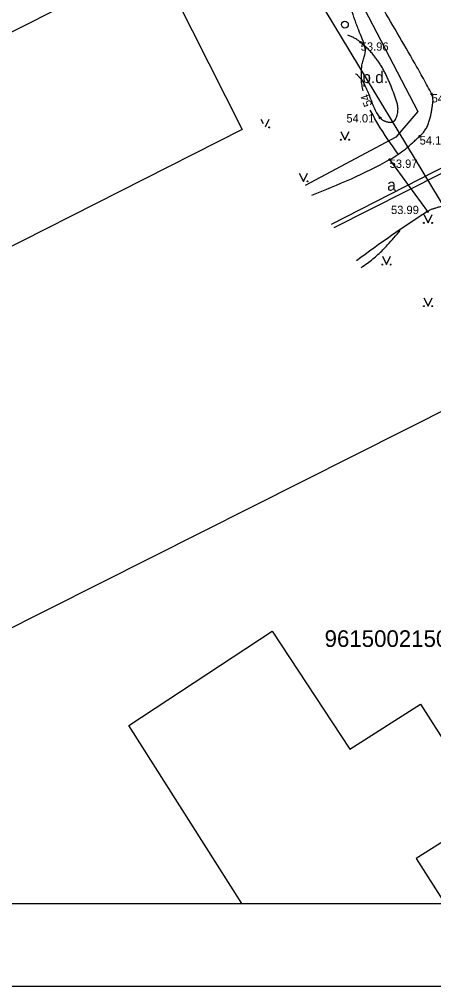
# Model space of a CAD drawing. Extents: x 578395 to 578590, y 418519 to 418816.
# Drawn here: x 578460.4 to 578485.3, y 418519.1 to 418577.2 of the extents above; entities that cross this region are included whole.
import ezdxf

# ---------------------------------------------------------------- set-up
doc = ezdxf.new("R2010")
doc.units = 0
for name, color, linetype in [('BUVE_EKAS_UZMR_####_#', 7, 'Continuous'), ('CELI_CMAL_####_####_#', 7, 'Continuous'), ('CELI_CSEG_####_TKST_#', 7, 'Continuous'), ('CELI_SEGL_####_####_#', 7, 'Continuous'), ('ELEK_VADP_ZSPR_####_#', 7, 'Continuous'), ('RAMI_PLAN_####_TKST_#', 7, 'Continuous'), ('RELJ_AATZ_####_TKST_#', 7, 'Continuous'), ('RELJ_ELEM_####_####_#', 7, 'Continuous'), ('RELJ_HORZ_####_TKST_#', 7, 'Continuous'), ('RELJ_HORZ_RESN_####_#', 7, 'Continuous'), ('ROBZ_UZMR_####_####_#', 7, 'Continuous'), ('ROBZ_UZMR_####_TKST_#', 7, 'Continuous'), ('TERT_DZOG_####_####_#', 7, 'Continuous'), ('TERT_ELEM_####_####_#', 7, 'Continuous'), ('TERT_IZMT_####_TKST_#', 7, 'Continuous'), ('TERT_KONT_####_####_#', 7, 'Continuous')]:
    doc.layers.add(name, color=color, linetype=linetype)

msp = doc.modelspace()

# ---------------------------------------------------------------- linework, layer by layer
at = {"layer": 'BUVE_EKAS_UZMR_####_#'}
for p, q in [((578449.6670000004, 418571.2860000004), (578468.6500000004, 418580.8699999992)), ((578468.6500000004, 418580.8699999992), (578473.8300000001, 418570.60999999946)), ((578473.8300000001, 418570.60999999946), (578454.6849999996, 418560.94400000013)), ((578467.0099999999, 418534.8000000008), (578475.6200000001, 418540.47000000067)), ((578475.6200000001, 418540.47000000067), (578480.2869999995, 418533.38299999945)), ((578480.2869999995, 418533.38299999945), (578484.5499999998, 418536.08999999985)), ((578484.5499999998, 418536.08999999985), (578488.6699999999, 418529.5999999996)), ((578473.7943231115, 418524.11118321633), (578467.0099999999, 418534.8000000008)), ((578488.6699999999, 418529.5999999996), (578484.2829999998, 418526.8149999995)), ((578484.2829999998, 418526.8149999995), (578486.009600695, 418524.11118321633))]:
    msp.add_line(p, q, dxfattribs=at)
at = {"layer": 'CELI_CMAL_####_####_#'}
for points in [[(578494.8535960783, 418568.01668911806), (578493.2220155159, 418570.92426636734), (578490.7633646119, 418575.52004860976), (578488.3310314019, 418580.13005654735), (578485.806, 418584.688), (578479.899, 418594.609), (578471.211, 418607.77900000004)], [(578478.0080904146, 418566.6710838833), (578482.69, 418568.81), (578483.6371195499, 418569.4394039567), (578484.068272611, 418569.823355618), (578484.2810717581, 418570.0190353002), (578484.495, 418570.212), (578484.5888582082, 418570.2964336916), (578484.6775343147, 418570.3860180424), (578484.7572642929, 418570.4852822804), (578484.8306615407, 418570.59113918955), (578484.9579047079, 418570.8222276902), (578485.0504891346, 418571.0667472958), (578485.1873221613, 418571.5887317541), (578485.2348780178, 418571.8514611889), (578485.274, 418572.107), (578485.293491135, 418572.4305135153), (578485.216, 418572.74100000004), (578484.9675876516, 418573.2094804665), (578484.7150127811, 418573.6745564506), (578484.1998261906, 418574.5962796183), (578483.1464606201, 418576.4185032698), (578482.0951147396, 418578.23622528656), (578481.5824527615, 418579.15232141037), (578481.0850000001, 418580.07800000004)], [(578489.5889319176, 418565.16186315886), (578489.474, 418565.3020000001), (578489.267083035, 418565.51501793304), (578489.032762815, 418565.6968825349), (578488.7774474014, 418565.85352000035), (578488.5075448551, 418565.9908565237), (578488.2313820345, 418566.0986606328), (578487.9459357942, 418566.1750680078), (578487.378, 418566.248), (578487.1568734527, 418566.23901611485), (578486.9359834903, 418566.22009073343), (578486.4948701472, 418566.1554153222), (578486.2726496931, 418566.1114777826), (578486.0524648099, 418566.05966290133), (578485.8335169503, 418566.0018115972), (578485.6150075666, 418565.93976478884), (578485.4446654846, 418565.89002460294), (578485.2759844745, 418565.8347055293), (578485.1135631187, 418565.76672488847), (578484.9620000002, 418565.679), (578480.6876626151, 418562.72429428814)]]:
    msp.add_spline(points, degree=3, dxfattribs=at)
at = {"layer": 'CELI_SEGL_####_####_#'}
msp.add_lwpolyline([(578482.69, 418568.81), (578484.9620000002, 418565.679)], dxfattribs=at)
at = {"layer": 'ELEK_VADP_ZSPR_####_#'}
for points in [[(578479.1866061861, 418564.9352270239), (578498.7070000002, 418574.895), (578493.2635, 418583.07450000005), (578485.065, 418590.96500000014)], [(578500, 418572.15726561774), (578498.8670000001, 418574.559), (578479.3351508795, 418564.7164329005)]]:
    msp.add_lwpolyline(points, dxfattribs=at)
at = {"layer": 'RAMI_PLAN_####_TKST_#'}
msp.add_line((578590.3507496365, 418519.1111832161), (578395.3507496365, 418519.1111832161), dxfattribs=at)
msp.add_lwpolyline([(578410.3507496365, 418811.11118321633), (578410.3507496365, 418524.11118321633), (578585.3507496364, 418524.1111832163), (578585.3507496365, 418811.1111832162)], close=True, dxfattribs=at)
at = {"layer": 'RELJ_ELEM_####_####_#'}
for centre in [(578480.951, 418575.8510000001), (578485.216, 418572.74100000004), (578482.118, 418571.31200000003), (578484.495, 418570.212), (578482.69, 418568.81), (578484.9620000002, 418565.679)]:
    msp.add_circle(centre, 0.05, dxfattribs=at)
at = {"layer": 'RELJ_HORZ_RESN_####_#'}
for points in [[(578481.104599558, 418572.9378226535), (578481.0609714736, 418573.10956859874), (578481.0067079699, 418573.43451407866), (578480.990463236, 418573.7622876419), (578480.9979566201, 418574.090225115), (578481.0149074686, 418574.4156623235), (578481.0328319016, 418574.55483890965), (578481.0672293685, 418574.6941406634), (578481.1565127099, 418574.97236401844), (578481.2248961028, 418575.2488210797), (578481.233168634, 418575.38591496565), (578481.2145181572, 418575.5220005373), (578481.0409450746, 418576.0563375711), (578480.8306514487, 418576.5822413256), (578480.7115594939, 418576.8943969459), (578480.6000072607, 418577.2098336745), (578480.3790120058, 418577.8401252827), (578480.1266457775, 418578.45226580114), (578479.8018886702, 418579.0254048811), (578479.5539200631, 418579.3872633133)], [(578483.215217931, 418569.11291567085), (578481.9822515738, 418570.95835540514), (578481.5227550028, 418571.7774811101)], [(578480.9681112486, 418562.3112165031), (578481.3559119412, 418562.58338076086), (578481.679588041, 418562.8362290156), (578481.9890979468, 418563.1032259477), (578482.5621302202, 418563.6826450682), (578483.3302647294, 418564.5510362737)]]:
    msp.add_spline(points, degree=3, dxfattribs=at)
at = {"layer": 'ROBZ_UZMR_####_####_#'}
for p, q in [((578491.6210000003, 418556.59699999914), (578468.2019999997, 418595.33000000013)), ((578440.8499999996, 418531.0700000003), (578491.6210000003, 418556.59699999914))]:
    msp.add_line(p, q, dxfattribs=at)
at = {"layer": 'TERT_DZOG_####_####_#'}
msp.add_lwpolyline([(578479.4280000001, 418578.971), (578480.4330000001, 418579.283), (578484.388, 418571.691), (578483.067, 418570.15), (578477.6151525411, 418567.24984907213)], dxfattribs=at)
at = {"layer": 'TERT_ELEM_####_####_#'}
for p, q in [((578474.9540631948, 418571.2418295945), (578475.0914509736, 418570.9670540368)), ((578475.2211542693, 418570.77601174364), (578475.4540631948, 418571.2418295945)), ((578479.75, 418570.5), (578480, 418570)), ((578480, 418570), (578480.25, 418570.5)), ((578477.25, 418568), (578477.5, 418567.5)), ((578477.5, 418567.5), (578477.75, 418568)), ((578484.75, 418565.5), (578485, 418565)), ((578485, 418565), (578485.25, 418565.5)), ((578482.25, 418563), (578482.5, 418562.5)), ((578482.5, 418562.5), (578482.75, 418563)), ((578484.75, 418560.5), (578485, 418560)), ((578485, 418560), (578485.25, 418560.5))]:
    msp.add_line(p, q, dxfattribs=at)
for centre, radius in [((578479.9972936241, 418576.9184505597), 0.20454262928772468), ((578475.4537832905, 418570.74137929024), 0.02630589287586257), ((578479.7497200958, 418569.99954969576), 0.02800000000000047), ((578480.2497200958, 418569.99954969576), 0.02630589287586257), ((578477.7497200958, 418567.49954969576), 0.02630589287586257), ((578484.7497200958, 418564.99954969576), 0.02800000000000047), ((578485.2497200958, 418564.99954969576), 0.02630589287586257), ((578482.2497200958, 418562.49954969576), 0.02800000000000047), ((578482.7497200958, 418562.49954969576), 0.02630589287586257), ((578484.7497200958, 418559.99954969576), 0.02800000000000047), ((578485.2497200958, 418559.99954969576), 0.02630589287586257)]:
    msp.add_circle(centre, radius, dxfattribs=at)
at = {"layer": 'TERT_KONT_####_####_#'}
msp.add_spline([(578480.6439999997, 418573.9610000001), (578480.644, 418573.961), (578480.7872207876, 418573.83994988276), (578480.9143389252, 418573.7044145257), (578481.1282300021, 418573.3972168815), (578481.2152087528, 418573.2226911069), (578481.2971338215, 418573.0464907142), (578481.3751421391, 418572.86875303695), (578481.4503706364, 418572.6896154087), (578481.5231401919, 418572.5064000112), (578481.5931146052, 418572.3221849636), (578481.6635808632, 418572.1381453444), (578481.7378259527, 418571.9554562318), (578481.9083603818, 418571.6150614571), (578482.061053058, 418571.38346377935), (578482.089112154, 418571.34734002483), (578482.118, 418571.31200000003), (578482.2012589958, 418571.2329157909), (578482.3078792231, 418571.16281235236), (578482.3690165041, 418571.13245687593), (578482.4314031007, 418571.1069087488), (578482.4949804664, 418571.08516078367), (578482.5596900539, 418571.06620579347), (578482.6215350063, 418571.0528064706), (578482.6847862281, 418571.0462312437), (578482.7481683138, 418571.04696592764), (578482.8104058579, 418571.0554963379), (578482.888568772, 418571.08031077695), (578482.9598096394, 418571.1238758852), (578482.9793366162, 418571.1427788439), (578482.997, 418571.16400000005), (578483.0706583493, 418571.2830877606), (578483.1260619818, 418571.4149189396), (578483.1853811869, 418571.7019888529), (578483.1815097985, 418571.9955643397), (578483.1705196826, 418572.06412499), (578483.1574409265, 418572.1323087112), (578483.121, 418572.266), (578483.038605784, 418572.50178676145), (578482.9543809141, 418572.7383703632), (578482.7759248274, 418573.2119051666), (578482.6792514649, 418573.4498726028), (578482.5749584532, 418573.6844192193), (578482.4640140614, 418573.9163036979), (578482.3473865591, 418574.1462847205), (578482.218085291, 418574.3798202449), (578482.0773399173, 418574.6057033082), (578481.9255599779, 418574.82449887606), (578481.7631550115, 418575.03677191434), (578481.5824371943, 418575.2517978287), (578481.3900823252, 418575.4554412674), (578481.1793566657, 418575.65636232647), (578481.067452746, 418575.7544981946), (578480.951, 418575.8510000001), (578480.7632441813, 418575.99011453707), (578480.6650105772, 418576.05347303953), (578480.563525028, 418576.11223581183), (578480.3693629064, 418576.2098107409), (578480.1693809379, 418576.29296165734)], degree=3, dxfattribs=at)

# ---------------------------------------------------------------- texts
at = {"layer": 'CELI_CSEG_####_TKST_#'}
msp.add_text('a', height=0.7, dxfattribs=at).set_placement((578482.5414396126, 418566.93627647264))
at = {"layer": 'RELJ_AATZ_####_TKST_#'}
for s, p in [('53.96', (578480.951, 418575.3510000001)), ('54.30', (578485.216, 418572.24100000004)), ('54.01', (578480.0924471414, 418571.0377584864)), ('54.14', (578484.495, 418569.712)), ('53.97', (578482.69, 418568.31)), ('53.99', (578482.7719791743, 418565.5341421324))]:
    msp.add_text(s, height=0.5, dxfattribs=at).set_placement(p)
at = {"layer": 'RELJ_HORZ_####_TKST_#'}
msp.add_text('54', height=0.49999999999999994, rotation=109.75049717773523, dxfattribs=at).set_placement((578481.6473718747, 418572.08785031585))
at = {"layer": 'ROBZ_UZMR_####_TKST_#'}
msp.add_text('96150021501', height=1, dxfattribs=at).set_placement((578478.7785292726, 418539.5238633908))
at = {"layer": 'TERT_IZMT_####_TKST_#'}
msp.add_text('p.d.', height=0.7, dxfattribs=at).set_placement((578481.0403312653, 418573.4046979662))

doc.saveas('drawing.dxf')
